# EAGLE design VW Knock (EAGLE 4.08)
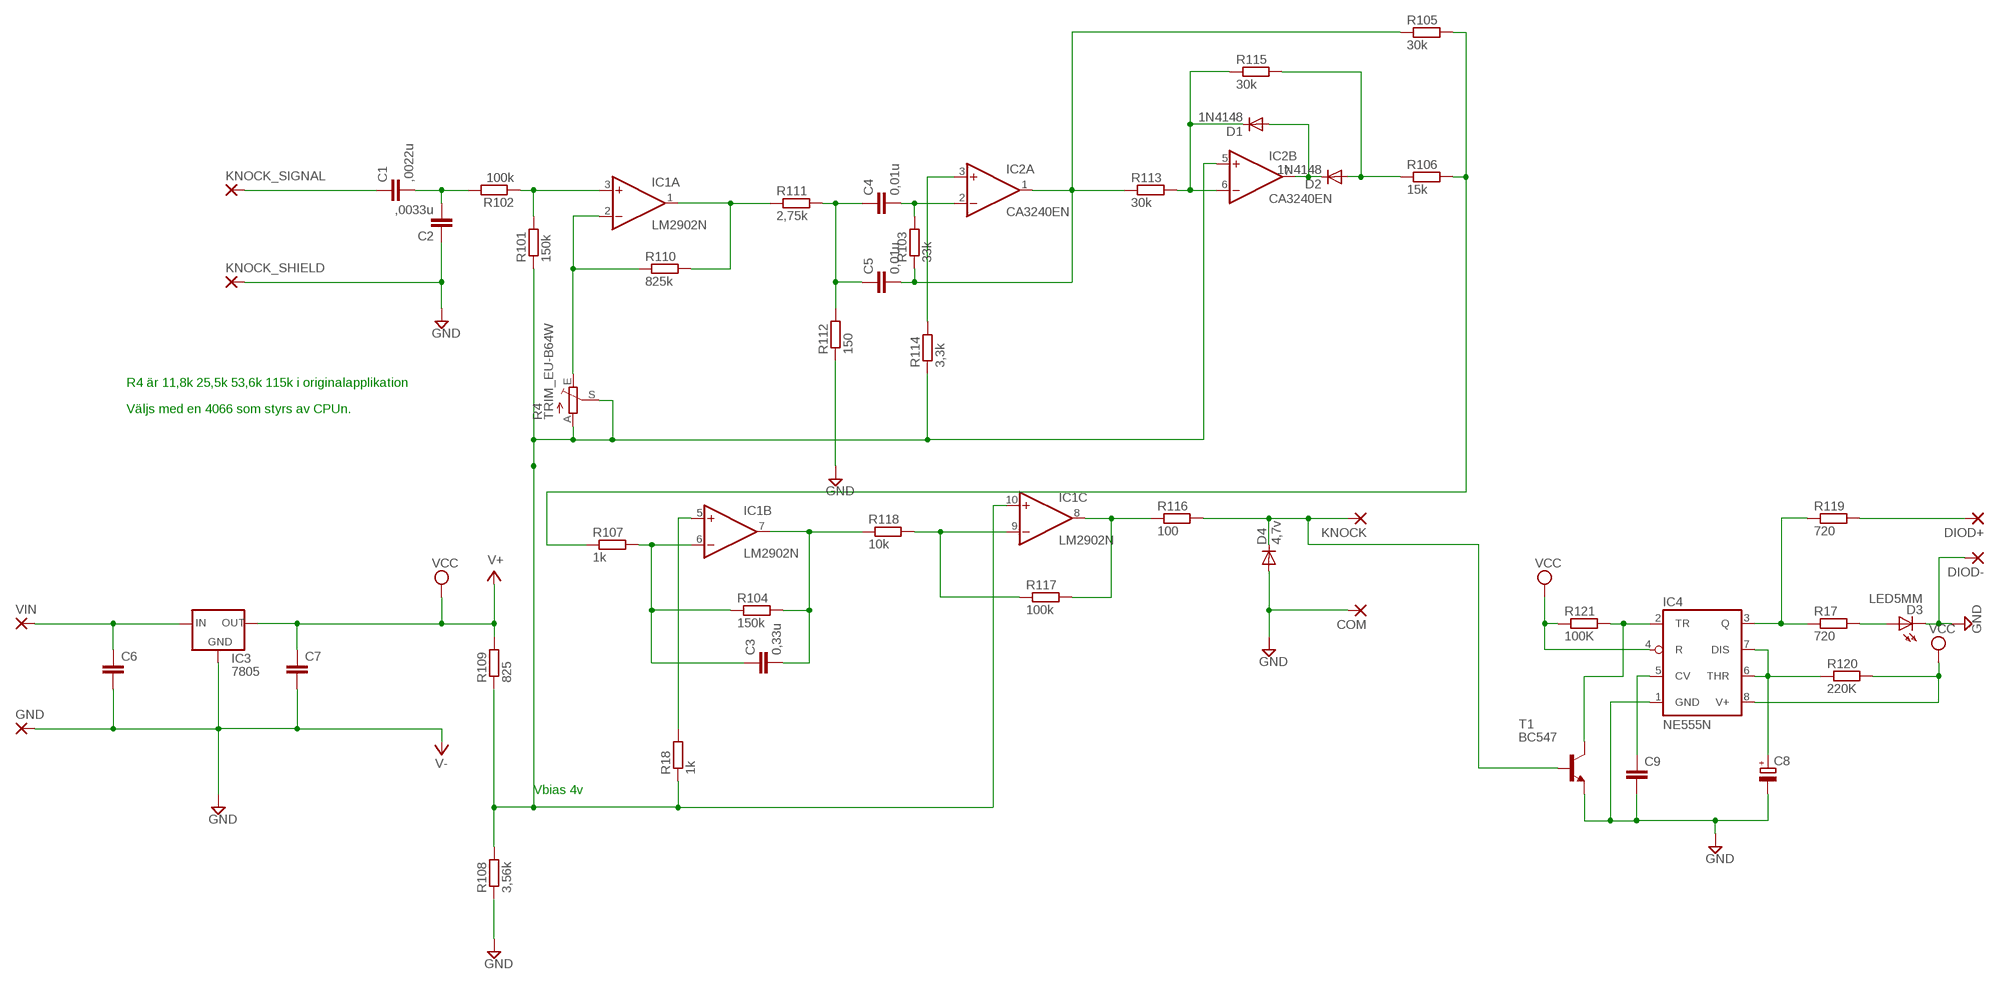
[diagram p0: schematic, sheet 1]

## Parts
C1  ,0022u  C-EU050-025X075  [C050-025X075]
C2  ,0033u  C-EU050-025X075  [C050-025X075]
C3  0,33u  C-EU050-025X075  [C050-025X075]
C4  0,01u  C-EU050-025X075  [C050-025X075]
C5  0,01u  C-EU050-025X075  [C050-025X075]
C6  C-EU050-025X075  [C050-025X075]
C7  C-EU050-025X075  [C050-025X075]
C8  CPOL-EUTT2D6  [TT2D6]
C9  C-EU050-025X075  [C050-025X075]
COM  2,54/1,0  [2,54/1,0]
D1  1N4148  [DO35-10]
D2  1N4148  [DO35-10]
D3  LED5MM  [LED5MM]
D4  4,7v  DIODE-D-7.5  [D-7.5]
DIOD+  2,15/1,0  [2,15/1,0]
DIOD-  2,15/1,0  [2,15/1,0]
GND  2,54/1,0  [2,54/1,0]
IC1  LM2902N  [DIL14]
IC2  CA3240EN  [DIL08]
IC3  7805  78LXX  [78LXX]
IC4  NE555N  [DIL08]
KNOCK  2,54/1,0  [2,54/1,0]
KNOCK_SHIELD  2,54/1,0  [2,54/1,0]
KNOCK_SIGNAL  2,54/1,0  [2,54/1,0]
R4  TRIM_EU-B64W  [B64W]
R17  720  R-EU_0207/7  [0207/7]
R18  1k  R-EU_0207/7  [0207/7]
R101  150k  R-EU_0207/7  [0207/7]
R102  100k  R-EU_0207/7  [0207/7]
R103  33k  R-EU_0207/7  [0207/7]
R104  150k  R-EU_0207/7  [0207/7]
R105  30k  R-EU_0207/7  [0207/7]
R106  15k  R-EU_0207/7  [0207/7]
R107  1k  R-EU_0207/7  [0207/7]
R108  3,56k  R-EU_0207/7  [0207/7]
R109  825  R-EU_0207/7  [0207/7]
R110  825k  R-EU_0207/7  [0207/7]
R111  2,75k  R-EU_0207/7  [0207/7]
R112  150  R-EU_0207/7  [0207/7]
R113  30k  R-EU_0207/7  [0207/7]
R114  3,3k  R-EU_0207/7  [0207/7]
R115  30k  R-EU_0207/7  [0207/7]
R116  100  R-EU_0207/7  [0207/7]
R117  100k  R-EU_0207/7  [0207/7]
R118  10k  R-EU_0207/7  [0207/7]
R119  720  R-EU_0207/7  [0207/7]
R120  220K  R-EU_0207/7  [0207/7]
R121  100K  R-EU_0207/7  [0207/7]
T1  BC547  [TO92]
VIN  2,54/1,0  [2,54/1,0]

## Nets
GND: C2.1 C6.2 C7.2 C8.- C9.2 COM.1(P) D3.K(C) D4.A DIOD-.1(P) GND.1(P) IC3.GND IC4.1(GND) KNOCK_SHIELD.1(P) R108.1 R112.1 T1.1(E) ; supply symbol labelled V-
N$1: C1.1 KNOCK_SIGNAL.1(P)
N$2: C1.2 C2.2 R102.2
N$3: IC1.2(A:-IN) R4.E R110.1
N$4: IC1.3(A:+IN) R101.2 R102.1
N$5: IC1.1(A:OUT) R110.2 R111.1
N$6: C4.2 IC2.2(A:-IN) R103.2
N$7: C6.1 IC3.IN VIN.1(P)
N$8: C4.1 C5.1 R111.2 R112.2
N$9: D1.C IC2.6(B:-IN) R113.2 R115.1
N$10: D3.A R17.2
N$11: IC2.3(A:+IN) R114.2
N$12: C5.2 IC2.1(A:OUT) R103.1 R105.1 R113.1
N$14: IC4.2(TR) R121.2 T1.3(C)
N$15: D1.A D2.C IC2.7(B:OUT)
N$16: D2.A R106.1 R115.2
N$19: R105.2 R106.2 R107.1
N$20: C8.+ IC4.6(THR) IC4.7(DIS) R120.1
N$21: IC1.5(B:+IN) R18.2
N$22: C3.1 IC1.6(B:-IN) R104.1 R107.2
N$24: C3.2 IC1.7(B:OUT) R104.2 R118.1
N$25: C9.1 IC4.5(CV)
N$26: IC4.3(Q) R17.1 R119.1
N$29: D4.C KNOCK.1(P) R116.2 T1.2(B)
N$30: IC1.9(C:-IN) R117.1 R118.2
N$32: IC1.8(C:OUT) R116.1 R117.2
N$33: DIOD+.1(P) R119.2
V+: C7.1 IC3.OUT R109.2 ; supply symbol labelled VCC
VBIAS: IC1.10(C:+IN) IC2.5(B:+IN) R4.A R4.S R18.1 R101.1 R108.2 R109.1 R114.1
VCC: IC4.4(R) IC4.8(V+) R120.2 R121.1
Unconnected: IC1.12(D:+IN) IC1.13(D:-IN) IC1.14(D:OUT)

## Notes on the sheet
- R4 är 11,8k 25,5k 53,6k 115k i originalapplikation
- Väljs med en 4066 som styrs av CPUn.
- Vbias 4v

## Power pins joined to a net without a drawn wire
GND: IC1.11(P:V-) IC2.4(P:V-)
V+: IC1.4(P:V+) IC2.8(P:V+)

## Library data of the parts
C1-C7 C9 = rcl:C-EU: CAPACITOR, European symbol
C8 = rcl:CPOL-EU: POLARIZED CAPACITOR, European symbol
COM GND KNOCK KNOCK_SHIELD KNOCK_SIGNAL VIN = wirepad:2,54/1,0: THROUGH-HOLE PAD
D1 D2 = diode:1N4148: DIODE
D3 = led:LED5MM: LED
D4 = diode:DIODE-: DIODE
DIOD+ DIOD- = wirepad:2,15/1,0: THROUGH-HOLE PAD
IC1 = linear:LM2902: COMPARATOR
IC2 = linear:CA3240E: OP AMP
IC3 = v-reg:78LXX: VOLTAGE REGULATOR
IC4 = linear:*555: TIMER
R4 = pot:TRIM_EU-: POTENTIOMETER
R17 R18 R101-R121 = rcl:R-EU_: RESISTOR, European symbol
T1 = transistor-npn:BC547: NPN TRANSISTOR

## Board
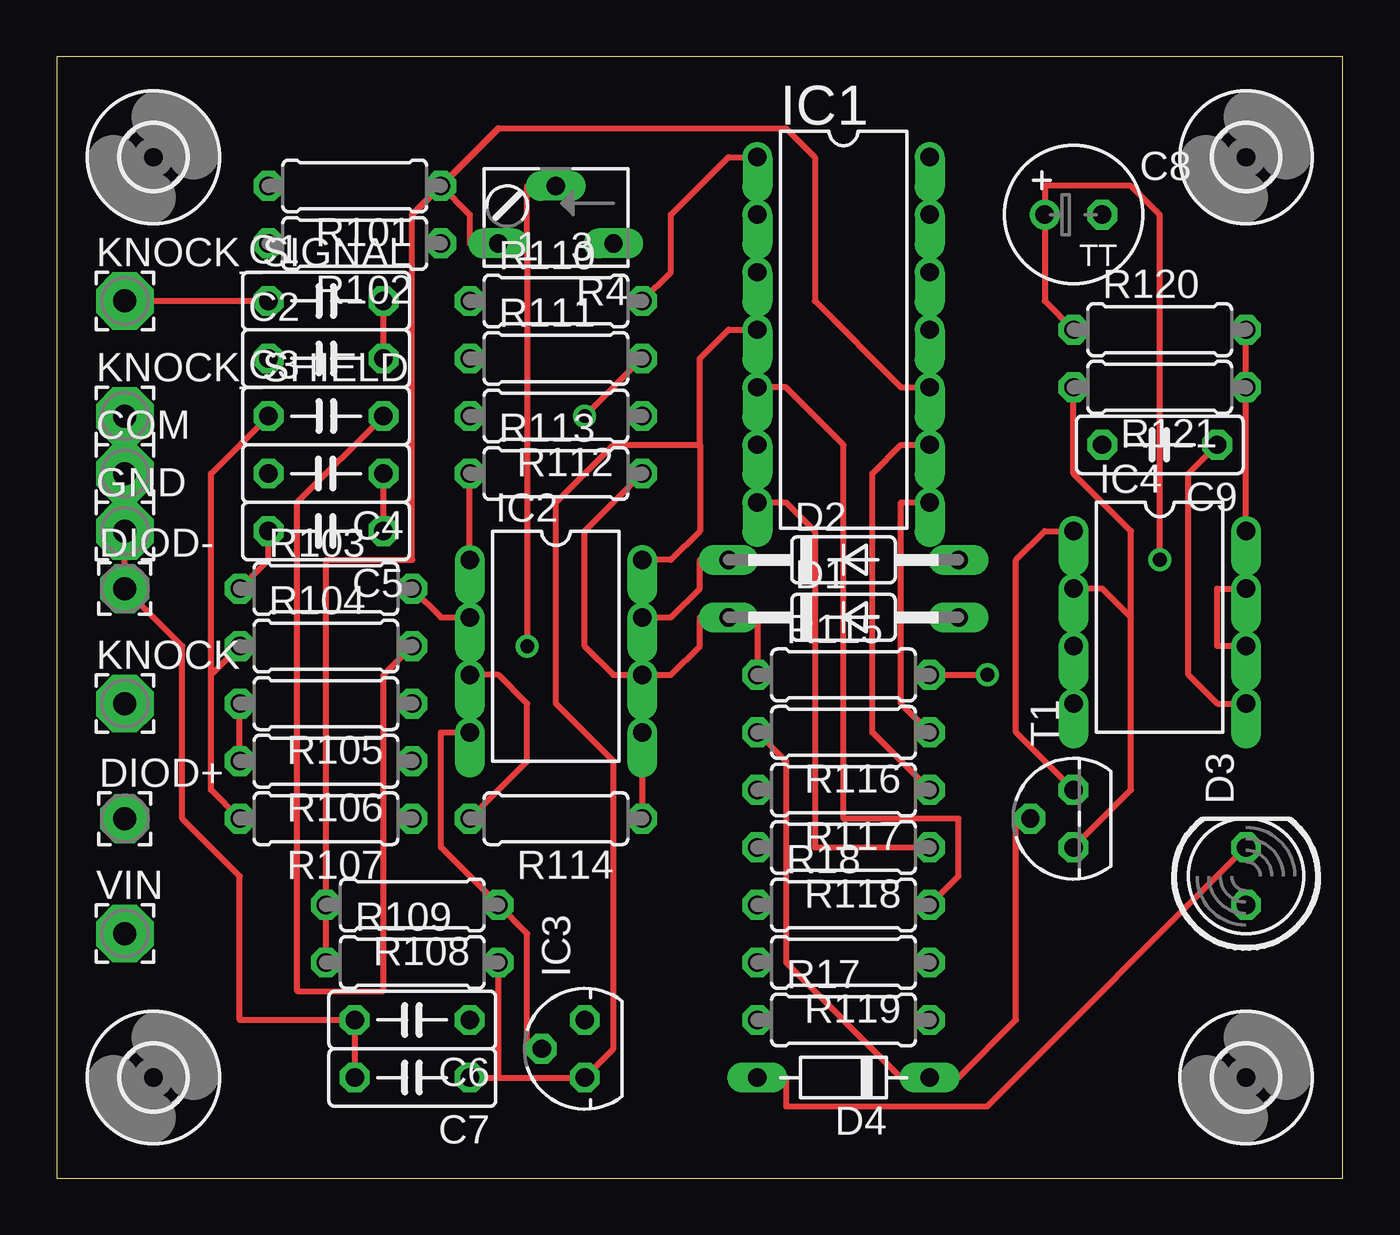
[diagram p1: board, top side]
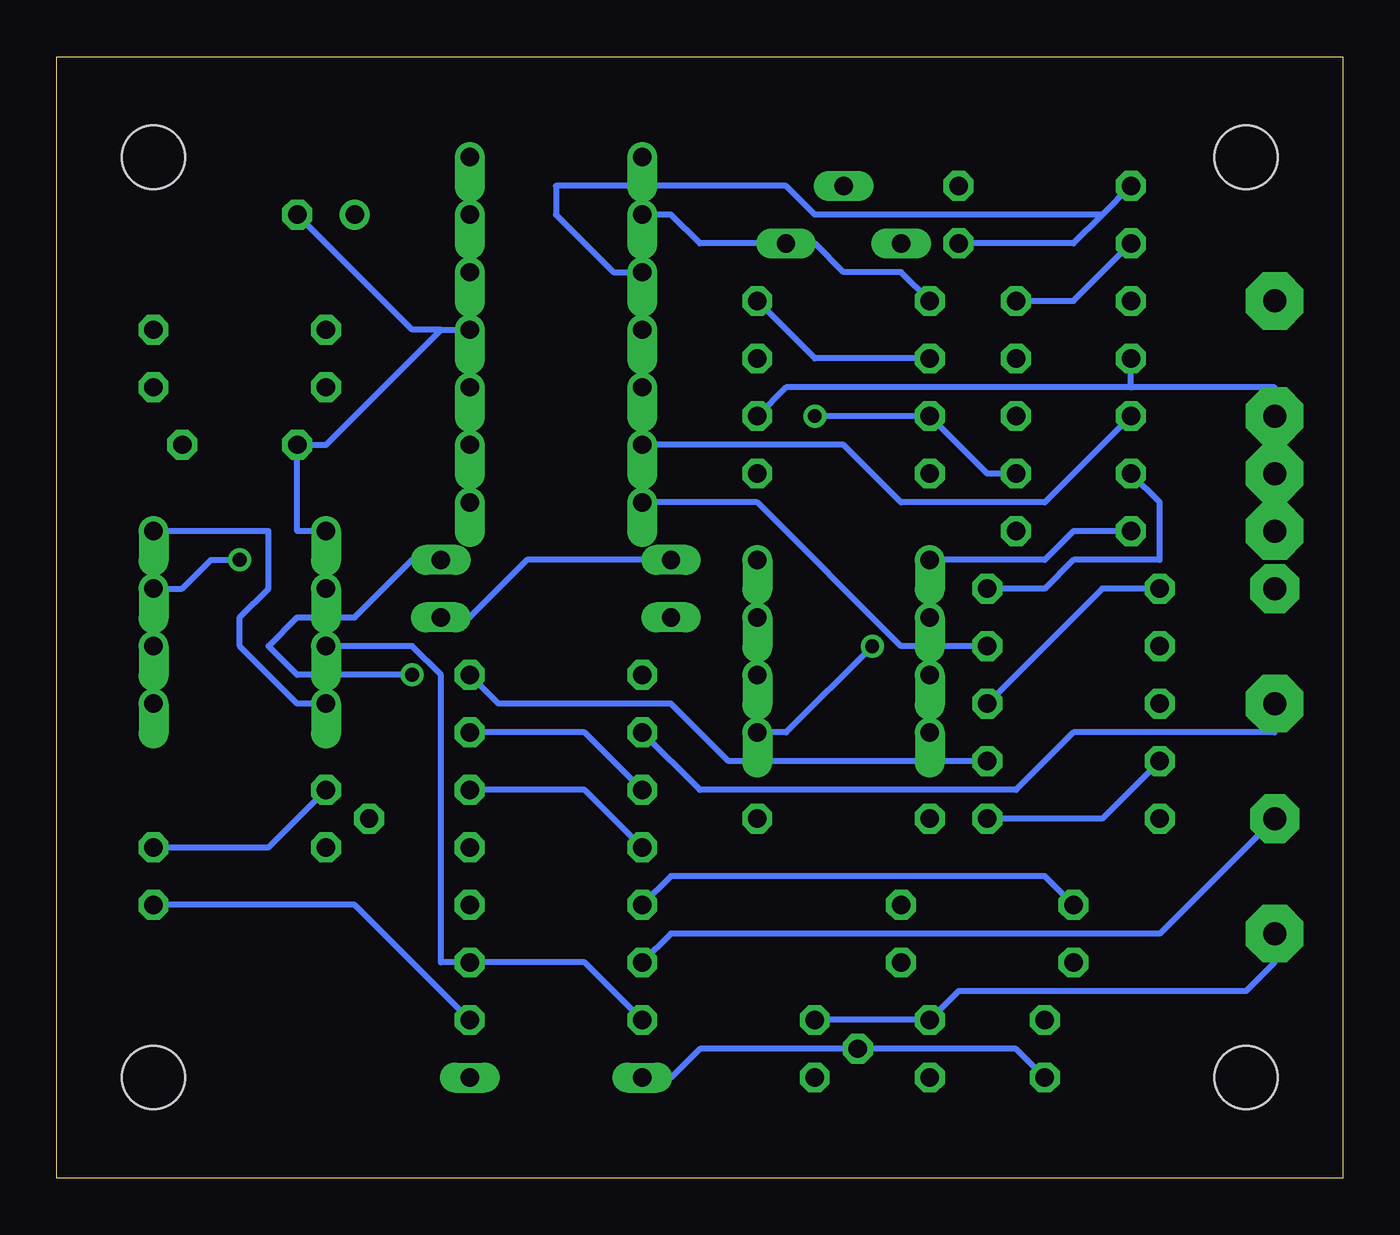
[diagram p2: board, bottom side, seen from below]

Size 56.82 x 49.52 mm. Coordinates in mm from the lower left corner, seen from the top.
Outline: 0,0 56.82,0 56.82,49.52 0,49.52 0,0
Copper layers used: Top, Bottom

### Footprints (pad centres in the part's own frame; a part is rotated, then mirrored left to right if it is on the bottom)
C050-025X075 = drill 0.813 octagon: 1 -2.54,0; 2 2.54,0
TT2D6 = drill 0.813 round: + -1.27,0 | drill 0.813 octagon: - 1.27,0
2,54/1,0 = drill 1.016 pad 2.54 octagon: 1 0,0
DO35-10 = drill 0.813 long: A 5.08,0; C -5.08,0
LED5MM = drill 0.813 octagon: A -1.27,0; K 1.27,0
D-7.5 = drill 0.813 long: A 3.81,0; C -3.81,0
2,15/1,0 = drill 1.016 pad 2.159 octagon: 1 0,0
DIL14 = drill 0.813 offset: 1 -7.62,-3.81; 2 -5.08,-3.81; 3 -2.54,-3.81; 4 0,-3.81; 5 2.54,-3.81; 6 5.08,-3.81; 7 7.62,-3.81; 8 7.62,3.81; 9 5.08,3.81; 10 2.54,3.81; 11 0,3.81; 12 -2.54,3.81; 13 -5.08,3.81; 14 -7.62,3.81
DIL08 = drill 0.813 offset: 1 -3.81,-3.81; 2 -1.27,-3.81; 3 1.27,-3.81; 4 3.81,-3.81; 5 3.81,3.81; 6 1.27,3.81; 7 -1.27,3.81; 8 -3.81,3.81
78LXX = drill 0.813 octagon: GND 0,1.905; IN 1.27,0; OUT -1.27,0
B64W = drill 0.813 long: A 2.54,0; E -2.54,0; S 0,-2.54
0207/7 = drill 0.813 octagon: 1 -3.81,0; 2 3.81,0
TO92 = drill 0.813 octagon: 1 1.27,0; 2 0,1.905; 3 -1.27,0
2,8 = hole 2.8: 0,0

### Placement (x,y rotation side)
C1  11.9,38.73 0 top
C2  11.9,36.19 0 top
C3  11.9,33.65 0 top
C4  11.9,31.11 180 top
C5  11.9,28.57 180 top
C6  15.71,6.98 180 top
C7  15.71,4.44 180 top
C8  44.92,42.54 0 top
C9  48.73,32.38 180 top
COM  3.01,31.11 0 top
D1  34.76,24.76 0 top
D2  34.76,27.3 0 top
D3  52.54,13.33 90 top
D4  34.76,4.44 180 top
DIOD+  3.01,15.87 0 top
DIOD-  3.01,26.03 0 top
GND  3.01,28.57 0 top
IC1  34.76,37.46 270 top
IC2  22.06,23.49 270 top
IC3  23.33,5.71 90 top
IC4  48.73,24.76 270 top
KNOCK  3.01,20.95 0 top
KNOCK_SHIELD  3.01,33.65 0 top
KNOCK_SIGNAL  3.01,38.73 0 top
R4  22.06,41.27 180 top
R17  34.76,6.98 0 top
R18  34.76,12.06 0 top
R101  13.17,43.81 180 top
R102  13.17,41.27 180 top
R103  11.9,26.03 0 top
R104  11.9,23.49 0 top
R105  11.9,20.95 180 top
R106  11.9,18.41 180 top
R107  11.9,15.87 180 top
R108  15.71,12.06 180 top
R109  15.71,9.52 0 top
R110  22.06,38.73 0 top
R111  22.06,36.19 0 top
R112  22.06,33.65 180 top
R113  22.06,31.11 0 top
R114  22.06,15.87 180 top
R115  34.76,22.22 0 top
R116  34.76,19.68 180 top
R117  34.76,17.14 180 top
R118  34.76,14.6 180 top
R119  34.76,9.52 180 top
R120  48.73,37.46 0 top
R121  48.73,34.92 180 top
T1  44.92,15.87 90 top
U$1  [2,8]  4.28,4.44 0 top
U$2  [2,8]  4.28,45.08 0 top
U$3  [2,8]  52.54,45.08 0 top
U$4  [2,8]  52.54,4.44 0 top
VIN  3.01,10.79 0 top

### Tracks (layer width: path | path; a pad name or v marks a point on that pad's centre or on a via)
GND
  Top 0.254: T1.1 42.38,19.68 42.38,27.3 43.65,28.57 IC4.1 | C7.2 C6.2 8.09,6.98 8.09,13.33 5.55,15.87 5.55,23.49 DIOD-.1 GND.1 COM.1 KNOCK_SHIELD.1 | IC3.GND 20.79,5.71 20.79,10.79 R108.1 16.98,14.6 16.98,19.68 IC2.4 | D3.K 41.11,3.17 32.22,3.17 32.22,4.44 D4.A
  Bottom 0.254: T1.1 47.46,14.6 D3.K | IC4.1 46.19,28.57 C9.2 44.92,32.38 39.84,37.46 | C8.- 41.11,37.46 39.84,37.46 | 39.84,37.46 IC1.11 | D4.A 29.68,4.44 28.41,5.71 IC3.GND 14.44,5.71 C7.2 | R112.1 24.6,34.92 9.36,34.92 | 9.36,34.92 3.01,34.92 KNOCK_SHIELD.1 | 9.36,34.92 C2.1
N$1
  Top 0.254: KNOCK_SIGNAL.1 C1.1
N$2
  Top 0.254: C2.2 C1.2
  Bottom 0.254: R102.2 11.9,38.73 C1.2
N$3
  Bottom 0.254: R110.1 19.52,40 22.06,40 23.33,41.27 R4.E 28.41,41.27 29.68,42.54 IC1.2
N$4
  Bottom 0.254: 10.63,42.54 11.9,41.27 R102.1 | R101.2 10.63,42.54 | 10.63,42.54 23.33,42.54 24.6,43.81 34.76,43.81 34.76,42.54 32.22,40 IC1.3
N$5
  Top 0.254: R110.2 27.14,40 27.14,42.54 29.68,45.08 IC1.1
  Bottom 0.254: R111.1 23.33,36.19 R110.2
N$6
  Top 0.254: R103.2 16.98,24.76 IC2.2
  Bottom 0.254: C4.2 8.09,29.84 8.09,27.3 11.9,27.3 13.17,26.03 R103.2
N$7
  Bottom 0.254: IC3.IN C6.1 16.98,8.25 4.28,8.25 3.01,9.52 VIN.1
N$8  (via drill 0.61)
  Top 0.254: C5.1 C4.1 | v23.33,33.65 R111.2
  Bottom 0.254: C4.1 15.71,31.11 R112.2 v23.33,33.65
N$9
  Top 0.254: R113.2 23.33,28.57 23.33,23.49 24.6,22.22 IC2.6 27.14,22.22 28.41,23.49 28.41,24.76 D1.C 30.95,24.76 R115.1
N$10
  Bottom 0.254: R17.2 43.65,12.06 D3.A
N$11
  Top 0.254: R114.2 20.79,18.41 20.79,20.95 19.52,22.22 IC2.3
N$12
  Top 0.254: IC2.1 R113.1 | R103.1 9.36,27.3 C5.2
  Bottom 0.254: R105.1 10.63,26.03 R103.1 | C5.2 11.9,28.57 13.17,27.3 IC2.1
N$14
  Top 0.254: T1.3 47.46,17.14 47.46,24.76 | 47.46,24.76 46.19,26.03 IC4.2 | R121.2 44.92,31.11 47.46,28.57 47.46,24.76
N$15
  Top 0.254: IC2.7 27.14,24.76 28.41,26.03 28.41,27.3 D2.C
  Bottom 0.254: D1.A 38.57,24.76 36.03,27.3 D2.C
N$16  (via drill 0.61)
  Top 0.254: R115.2 v41.11,22.22
  Bottom 0.254: R106.1 27.14,18.41 29.68,20.95 37.3,20.95 R115.2 | v41.11,22.22 46.19,22.22 47.46,23.49 46.19,24.76 43.65,24.76 41.11,27.3 D2.A
N$19
  Top 0.254: R106.2 R105.2
  Bottom 0.254: R107.1 10.63,15.87 R106.2
N$20  (via drill 0.61)
  Top 0.254: IC4.6 51.27,23.49 51.27,26.03 IC4.7 | R120.1 43.65,38.73 C8.+ 43.65,43.81 47.46,43.81 48.73,42.54 v48.73,27.3
  Bottom 0.254: v48.73,27.3 50,27.3 51.27,26.03 IC4.7
N$21
  Top 0.254: R18.2 39.84,13.33 39.84,15.87 34.76,15.87 34.76,32.38 32.22,34.92 IC1.5
N$22
  Top 0.254: R107.2 6.82,17.14 6.82,22.22 | 6.82,22.22 R104.1 | C3.1 6.82,31.11 6.82,22.22
  Bottom 0.254: C3.1 13.17,29.84 19.52,29.84 22.06,32.38 IC1.6
N$24
  Top 0.254: R118.1 33.49,14.6 33.49,28.57 32.22,29.84 IC1.7 | C3.2 10.63,29.84 10.63,8.25 14.44,8.25 14.44,22.22 R104.2
  Bottom 0.254: R104.2 19.52,23.49 25.87,29.84 IC1.7
N$25
  Top 0.254: C9.1 50,31.11 50,22.22 51.27,20.95 IC4.5
N$26
  Bottom 0.254: R17.1 33.49,9.52 R119.1 39.84,9.52 39.84,22.22 41.11,23.49 IC4.3
N$29
  Top 0.254: T1.2 42.38,15.87 42.38,6.98 39.84,4.44 D4.C 37.3,4.44 32.22,9.52 32.22,18.41 R116.2
  Bottom 0.254: R116.2 28.41,17.14 14.44,17.14 11.9,19.68 3.01,19.68 KNOCK.1
N$30
  Top 0.254: R117.1 36.03,19.68 36.03,31.11 37.3,32.38 IC1.9
  Bottom 0.254: R118.2 33.49,17.14 R117.1
N$32
  Top 0.254: R116.1 37.3,20.95 37.3,29.84 IC1.8
  Bottom 0.254: R117.2 33.49,19.68 R116.1
N$33
  Bottom 0.254: R119.2 29.68,10.79 8.09,10.79 DIOD+.1
V+
  Top 0.254: 19.52,4.44 IC3.OUT 24.6,5.71 24.6,18.41 22.06,20.95 22.06,29.84 24.6,32.38 28.41,32.38 | C7.1 19.52,4.44 | 19.52,4.44 R109.2 | 28.41,32.38 28.41,36.19 29.68,37.46 IC1.4 | 28.41,32.38 28.41,28.57 27.14,27.3 IC2.8
VBIAS  (via drill 0.61)
  Top 0.254: IC2.5 R114.1 | 20.79,41.27 20.79,43.81 R4.S | R101.1 18.25,42.54 18.25,41.27 R4.A 20.79,41.27 | 20.79,41.27 v20.79,23.49 | R109.1 R108.2 11.9,27.3 15.71,27.3 15.71,42.54 | 19.52,46.35 32.22,46.35 33.49,45.08 33.49,38.73 37.3,34.92 IC1.10
  Top 0.305: 15.71,42.54 R101.1 19.52,46.35
  Bottom 0.254: v20.79,23.49 24.6,19.68 IC2.5 | R18.1 29.68,13.33 13.17,13.33 R108.2
VCC
  Top 0.254: R120.2 R121.1 IC4.8
  Bottom 0.254: IC4.4 46.19,20.95 48.73,23.49 48.73,24.76 47.46,26.03 47.46,28.57 IC4.8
